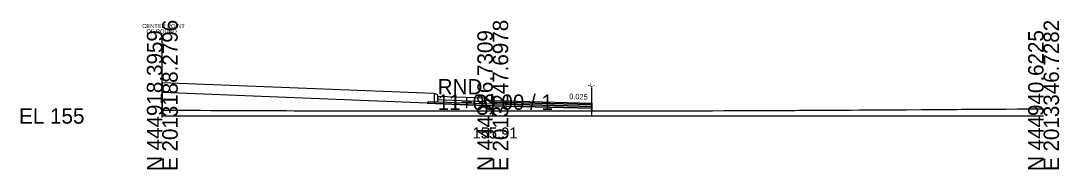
# Model space of a CAD drawing. Extents: x -26 to 163, y -10 to 7518.
# Drawn here: x -25.7 to 162.8, y 1990.3 to 2017.3 of the extents above; entities that cross this region are included whole.
import ezdxf

# ---------------------------------------------------------------- set-up
doc = ezdxf.new("R2010")
doc.units = 0
for name, color, linetype in [('Exist Cross Section Cell', 7, 'Continuous'), ('Exist XS Center Line Elevation Label', 7, 'Continuous'), ('Exist XS Ground Line', 7, 'Continuous'), ('Prop CMT Conc Surface', 7, 'Continuous'), ('Prop CMT Concrete Structures', 7, 'Continuous'), ('Prop CMT Pvmt Course 1', 7, 'Continuous'), ('Prop CMT Pvmt Course 1 CG', 7, 'Continuous'), ('Prop CMT Pvmt Course 2', 7, 'Continuous'), ('Prop CMT Pvmt Course 3', 7, 'Continuous'), ('Prop CMT Pvmt Surface', 7, 'Continuous'), ('Prop CMT Shear Line', 7, 'Continuous'), ('Prop CMT Shear Line Text', 7, 'Continuous'), ('Prop CMT Slope Grass', 7, 'Continuous'), ('Prop CMT Subgrade Earthwork', 7, 'Continuous'), ('Prop XS Earthwork Shape', 7, 'Continuous'), ('Prop XS SE Text', 7, 'Continuous')]:
    doc.layers.add(name, color=color, linetype=linetype)

msp = doc.modelspace()

# ---------------------------------------------------------------- linework, layer by layer
at = {"layer": 'Exist Cross Section Cell'}
for p, q in [((60, 2000), (60, 2003.91)), ((0, 2000), (60, 2000)), ((60, 2000), (160, 2000))]:
    msp.add_line(p, q, dxfattribs=at)
at = {"layer": 'Exist XS Ground Line'}
msp.add_lwpolyline([(0, 2001.05), (0.38, 2001.05), (1.25, 2001.05), (2.59, 2001.05), (3.76, 2001.04), (5.32, 2001.03), (6.28, 2001.03), (7.01, 2001.03), (8.81, 2001.02), (11.35, 2001.01), (12.1, 2001.01), (13.87, 2000.99), (15.88, 2000.99), (16.39, 2000.99), (17.07, 2000.99), (18.91, 2000.98), (20.29, 2000.98), (21.43, 2000.97), (22.51, 2000.97), (23.97, 2000.96), (24.73, 2000.96), (26.5, 2000.96), (26.95, 2000.96), (29.15, 2000.94), (30.11, 2000.94), (31.53, 2000.94), (33.58, 2000.93), (34.07, 2000.93), (34.71, 2000.93), (36.59, 2000.93), (37.64, 2000.93), (39.1, 2000.93), (40.21, 2000.93), (41.64, 2000.92), (42.44, 2000.92), (44.17, 2000.92), (46.85, 2000.92), (48.08, 2000.92), (49.31, 2000.92), (51.32, 2000.92), (52, 2000.91), (53.58, 2000.92), (54.66, 2000.92), (55.9, 2000.92), (56.61, 2000.91), (58.17, 2000.91), (59.09, 2000.91), (60, 2000.91), (60.95, 2000.91), (61.58, 2000.91), (63.7, 2000.92), (64.36, 2000.92), (66.73, 2000.92), (68.57, 2000.92), (69.07, 2000.92), (69.4, 2000.92), (71.92, 2000.92), (73.96, 2000.92), (74.44, 2000.92), (76.21, 2000.92), (76.96, 2000.92), (78.4, 2000.92), (79.49, 2000.92), (80.54, 2000.92), (82.29, 2000.92), (84.02, 2000.92), (84.65, 2000.92), (87.07, 2000.93), (88.93, 2000.94), (89.61, 2000.94), (90.29, 2000.95), (91.5, 2000.95), (92.12, 2000.95), (92.72, 2000.95), (94.29, 2000.95), (94.66, 2000.95), (95.26, 2000.96), (96.92, 2000.96), (97.61, 2000.96), (99.56, 2000.96), (99.92, 2000.96), (101.92, 2000.97), (102.28, 2000.97), (104.75, 2000.98), (106.62, 2000.99), (107.28, 2000.99), (108.15, 2001), (109.79, 2001.01), (111.04, 2001.01), (112.33, 2001.02), (113.26, 2001.02), (114.86, 2001.02), (115.48, 2001.03), (117.59, 2001.04), (119.91, 2001.05), (122.11, 2001.06), (122.42, 2001.06), (122.83, 2001.06), (124.95, 2001.08), (126.53, 2001.09), (127.47, 2001.09), (128.7, 2001.1), (130, 2001.11), (130.95, 2001.11), (132.53, 2001.12), (133.2, 2001.13), (135.03, 2001.14), (137.9, 2001.15), (140.09, 2001.17), (142.04, 2001.19), (142.62, 2001.19), (144.25, 2001.2), (145.14, 2001.21), (146.46, 2001.22), (147.67, 2001.23), (149.26, 2001.24), (150.19, 2001.24), (150.87, 2001.25), (152.72, 2001.26), (153.12, 2001.26), (155.24, 2001.27), (155.85, 2001.27), (157.76, 2001.29), (158.07, 2001.29), (160, 2001.3)], dxfattribs=at)
at = {"layer": 'Prop CMT Conc Surface'}
for points in [[(50, 2003.75), (49.96, 2003.85), (49.85, 2003.89), (49.34, 2004.08)], [(50, 2003.58), (50, 2003.75)], [(60, 2002.79), (59.25, 2002.81), (59.25, 2002.97), (58.5, 2003.22)]]:
    msp.add_lwpolyline(points, dxfattribs=at)
at = {"layer": 'Prop CMT Concrete Structures'}
for points in [[(50, 2003.75), (49.96, 2003.85), (49.85, 2003.89), (49.34, 2004.08)], [(49.34, 2004.08), (49.34, 2002.58)], [(49.34, 2002.58), (50, 2002.58)], [(50, 2003.58), (50, 2003.75)], [(50, 2002.58), (50, 2003.58)], [(50, 2003.58), (50, 2003)], [(58.5, 2003.22), (50, 2003.56)], [(50, 2002.98), (58.5, 2002.64)], [(60, 2002.79), (59.25, 2002.81), (59.25, 2002.97), (58.5, 2003.22)], [(58.5, 2003.22), (58.5, 2002.24)], [(58.5, 2002.64), (58.5, 2003.22)], [(58.5, 2002.24), (60, 2002.2)], [(60, 2002.2), (60, 2002.79)]]:
    msp.add_lwpolyline(points, dxfattribs=at)
at = {"layer": 'Prop CMT Pvmt Course 1'}
for points in [[(60, 2002.79), (78, 2002.33)], [(60, 2002.54), (60, 2002.79)], [(78, 2002.08), (60, 2002.54)], [(78, 2002.33), (78, 2002.08)]]:
    msp.add_lwpolyline(points, dxfattribs=at)
msp.add_lwpolyline([(60, 2002.54), (60, 2002.66), (60, 2002.66), (60, 2002.54)], close=True, dxfattribs=at)
at = {"layer": 'Prop CMT Pvmt Course 1 CG'}
for points in [[(60, 2001.87), (60, 2002.2)], [(78, 2001.42), (78, 2001.75)]]:
    msp.add_lwpolyline(points, dxfattribs=at)
at = {"layer": 'Prop CMT Pvmt Course 2'}
for points in [[(60, 2002.2), (60, 2002.54)], [(60, 2002.54), (78, 2002.08)], [(78, 2001.75), (60, 2002.2)], [(78, 2002.08), (78, 2001.75)]]:
    msp.add_lwpolyline(points, dxfattribs=at)
at = {"layer": 'Prop CMT Pvmt Course 3'}
for points in [[(50, 2002.58), (58.5, 2002.24)], [(60, 2002.2), (78, 2001.75)], [(60, 2001.87), (60, 2002.2)], [(78, 2001.42), (60, 2001.87)], [(78, 2001.75), (78, 2001.42)]]:
    msp.add_lwpolyline(points, dxfattribs=at)
at = {"layer": 'Prop CMT Pvmt Surface'}
msp.add_lwpolyline([(60, 2002.79), (78, 2002.33)], dxfattribs=at)
at = {"layer": 'Prop CMT Shear Line'}
for p, q in [((0, 1999.73), (0, 2014.73)), ((78, 2000.16), (78, 2005.17))]:
    msp.add_line(p, q, dxfattribs=at)
at = {"layer": 'Prop CMT Slope Grass'}
for p, q in [((49.34, 2004.06), (0, 2006.04)), ((48.06, 2002.35), (0, 2004.27))]:
    msp.add_line(p, q, dxfattribs=at)
at = {"layer": 'Prop CMT Subgrade Earthwork'}
for p, q in [((0, 2006.04), (0, 2001.05)), ((48.34, 2002.62), (48.06, 2002.35)), ((78, 2002.33), (78, 2001.42)), ((78, 2001.42), (78, 2000.92))]:
    msp.add_line(p, q, dxfattribs=at)
for points in [[(48.06, 2002.35), (60, 2001.87)], [(48.34, 2002.62), (49.34, 2002.58)], [(60, 2001.87), (78, 2001.42)]]:
    msp.add_lwpolyline(points, dxfattribs=at)
at = {"layer": 'Prop XS Earthwork Shape'}
msp.add_lwpolyline([(69.4, 2000.92), (71.92, 2000.92), (73.96, 2000.92), (74.44, 2000.92), (76.21, 2000.92), (76.96, 2000.92), (78, 2000.92), (78, 2001.42), (60, 2001.87), (48.06, 2002.35), (0, 2004.27), (0, 2001.05), (0.38, 2001.05), (1.25, 2001.05), (2.59, 2001.05), (3.76, 2001.04), (5.32, 2001.03), (6.28, 2001.03), (7.01, 2001.03), (8.81, 2001.02), (11.35, 2001.01), (12.1, 2001.01), (13.87, 2000.99), (15.88, 2000.99), (16.39, 2000.99), (17.07, 2000.99), (18.91, 2000.98), (20.29, 2000.98), (21.43, 2000.97), (22.51, 2000.97), (23.97, 2000.96), (24.73, 2000.96), (26.5, 2000.96), (26.95, 2000.96), (29.15, 2000.94), (30.11, 2000.94), (31.53, 2000.94), (33.58, 2000.93), (34.07, 2000.93), (34.71, 2000.93), (36.59, 2000.93), (37.64, 2000.93), (39.1, 2000.93), (40.21, 2000.93), (41.64, 2000.92), (42.44, 2000.92), (44.17, 2000.92), (46.85, 2000.92), (48.08, 2000.92), (49.31, 2000.92), (51.32, 2000.92), (52, 2000.91), (53.58, 2000.92), (54.66, 2000.92), (55.9, 2000.92), (56.61, 2000.91), (58.17, 2000.91), (59.09, 2000.91), (60, 2000.91), (60.95, 2000.91), (61.58, 2000.91), (63.7, 2000.92), (64.36, 2000.92), (66.73, 2000.92), (68.57, 2000.92), (69.07, 2000.92)], close=True, dxfattribs=at)

# ---------------------------------------------------------------- texts
at = {"layer": 'Exist Cross Section Cell'}
for s, p in [('E 2013188.2796', (2.8, 1990)), ('E 2013247.6978', (62.8, 1990)), ('N 444918.3959', (0, 1990)), ('N 444926.7309', (60, 1990)), ('N 444940.6225', (160, 1990)), ('E 2013346.7282', (162.8, 1990))]:
    msp.add_text(s, height=2.8, rotation=90, dxfattribs=at).set_placement(p)
for s, p in [('RND', (50, 2003.91)), ('11+00.00 / 1', (50, 2001.11)), ('EL 155', (-26, 1998.6))]:
    msp.add_text(s, height=2.8, dxfattribs=at).set_placement(p)
at = {"layer": 'Exist XS Center Line Elevation Label'}
msp.add_text('155.91', height=2, dxfattribs=at).set_placement((56.32, 1995.91))
at = {"layer": 'Prop CMT Shear Line Text'}
for s, p in [('CENTER POINT', (-3.64, 2015.98)), ('OF ROUND', (-2.88, 2015)), ('-L-', (77.27, 2005.29))]:
    msp.add_text(s, height=0.75, dxfattribs=at).set_placement(p)
at = {"layer": 'Prop XS SE Text'}
msp.add_text('0.025', height=1, rotation=358.5613, dxfattribs=at).set_placement((73.87, 2003.06))

doc.saveas('drawing.dxf')
